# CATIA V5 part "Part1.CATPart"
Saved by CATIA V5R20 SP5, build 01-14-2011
Part number: 凸缘压片
Bounding box of the stored display mesh (mm): x -97.094 to 86.526, y 0 to 116.467, z 0 to 30
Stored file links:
  E:\180522132\3.8卡瓦\Part1.CATPart
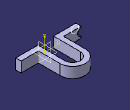
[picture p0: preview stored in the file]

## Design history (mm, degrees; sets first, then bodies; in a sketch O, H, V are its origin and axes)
Body1 (main body)
  Sketch1 on xy-plane, origin (0, 0, 0), H (1, 0, 0), V (0, 1, 0)
    arc A1 centre (0, 79.9411) radius 22.5599 from (22.5599, 79.9411) to (-22.5599, 79.9411) ccw
    point P1 (0, 79.9411)
    arc A2 centre (0, 79.9411) radius 36.5259 from (36.5259, 79.9411) to (-36.5259, 79.9411) ccw
    line L1 (-36.5259, 79.9411) -> (-36.5259, 17.6228)
    line L2 (-22.5599, 79.9411) -> (-22.5599, 2.2986)
    line L3 (22.5599, 79.9411) -> (22.5599, 2.2986)
    line L4 (36.5259, 79.9411) -> (36.5259, 17.6228)
    line L5 (-36.5259, 17.6228) -> (-86.5259, 17.6228)
    line L6 (-86.5259, 17.6228) -> (-86.5259, 2.2986)
    line L7 (-86.5259, 2.2986) -> (-22.5599, 2.2986)
    line L8 (86.5259, 2.2986) -> (86.5259, 17.6228)
    point P13 (86.5259, 17.6228)
    line L9 (86.5259, 17.6228) -> (36.5259, 17.6228)
    line L10 (22.5599, 2.2986) -> (86.5259, 2.2986)
    length L5 = 50
    length L9 = 50
    coincidence: P1 V, P13 L5, L7 L10
    tangency: L1 A2, L2 A1, L3 A1, L4 A2
    horizontal: L5 H, L7 H, L9 H, L10 H
    vertical: L6 V, L8 V
  Pad1: profile Sketch1, direction (0, 0, 1), length 30
  Sketch2 on zx-plane, origin (0, 0, 0), H (-1, 0, 0), V (0, 0, 1)
    circle A1 centre (86.3341, 14.3026) radius 10.7597
  Sketch3 on face of Pad1 from Sketch1.L5, origin (-71.7101, 17.6228, 21.1105), H (1, 0, 0), V (0, 0, -1)
    point P1 (-15.4143, 5.8911)
  Hole1: placed by Sketch3, at (-87.1244, 17.6228, 15.2195) direction (0, -1, 0), diameter 20, depth 10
